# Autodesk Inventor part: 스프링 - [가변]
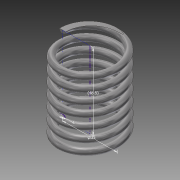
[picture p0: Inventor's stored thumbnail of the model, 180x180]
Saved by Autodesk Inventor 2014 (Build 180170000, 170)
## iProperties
Created: 2014-12
Part Number: 스프링 - [가변]
Material: 강철, 탄소
Document SubType Name: Modeling
Designer: basic
Density: 7.87 g/cm^3
Appearance: 반연마
Mass: 74.7925 g
Surface Area: 96.3926 cm^2
Volume: 9.50349 cm^3
Author: basic
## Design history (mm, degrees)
sketch "스케치1"
  geometry: L1 (0, 0)-(17.5, 0); L2 (17.5, 0)-(17.5, 48.5); L3 (17.5, 48.5)-(0, 48.5); L4 (0, 48.5)-(0, 0); C1 r 2 at (17.5, 0)
  constraints: 8 end point, 2 parallel, 1 centre point, 1 coincident, 1 horizontal, 1 perpendicular
  dimensions: "d1" = 48.5 distance of L3.end L1.start (derived); "d2" = 35 diameter of L2 L4; "d3" = 4 diameter of C1
feature "코일1" sketch "스케치1" pitch "d4" = 10; turns "d6" = 7; dims "d5" = 48.5 (= d1), "d7" = 0, angle "d8" = 90 deg, angle "d9" = 90 deg, "d10" = 0, "d11" = 0
sketch "스케치2"
  geometry: L1 (-19.5, 0)-(-15.5, 0) reference; 1 further point
  constraints: 1 horizontal alignment
extrude "돌출1" cut sketch "스케치2" distance "d12" = 10; taper "d13" = 0 deg
node "작업 평면1"
sketch "스케치3"
  geometry: L1 (2, 0)-(-2, 0) reference; 1 further point
  constraints: 1 horizontal alignment
extrude "돌출2" cut sketch "스케치3" distance "d15" = 10; taper "d16" = 0 deg
node "솔리드1"
node "절단 모서리 투영1"
node "절단 모서리 투영2"
other parameters: "d14" = 0
